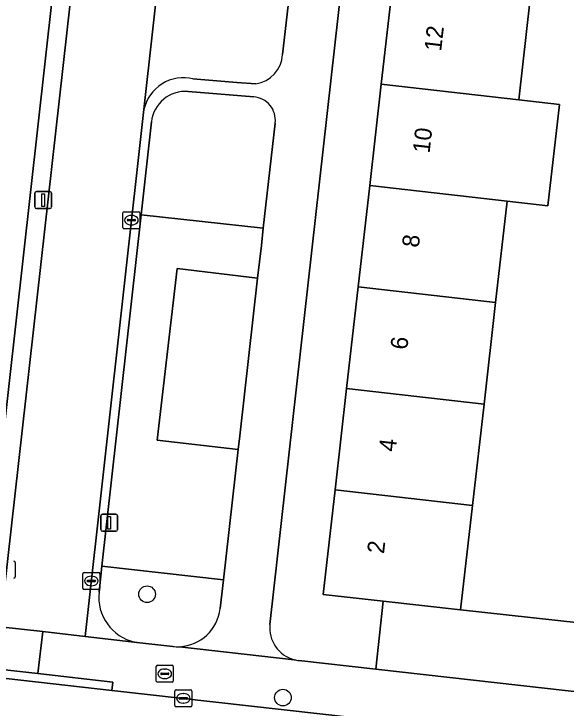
# Model space of a CAD drawing. Extents: x 161928 to 163071, y 386474 to 387428.
# Drawn here: x 162210.18 to 162242.64, y 386843.61 to 386884.42 of the extents above; entities that cross this region are included whole.
import ezdxf

# ---------------------------------------------------------------- set-up
doc = ezdxf.new("R2010")
doc.units = 0
for name, color, linetype in [('IMGEO_Boom', 7, 'Continuous'), ('IMGEO_Brandkraan', 7, 'Continuous'), ('IMGEO_Erf', 7, 'Continuous'), ('IMGEO_Groenvoorziening', 7, 'Continuous'), ('IMGEO_Hek', 7, 'Continuous'), ('IMGEO_Kolk', 7, 'Continuous'), ('IMGEO_Lichtmast', 7, 'Continuous'), ('IMGEO_Pand', 7, 'Continuous'), ('IMGEO_Pand_nummerreeks', 7, 'Continuous'), ('IMGEO_Parkeervlak_open', 7, 'Continuous'), ('IMGEO_Rijbaan_lokaal_open', 7, 'Continuous'), ('IMGEO_Voetpad_open', 7, 'Continuous')]:
    doc.layers.add(name, color=color, linetype=linetype)

msp = doc.modelspace()

# ---------------------------------------------------------------- linework, layer by layer
at = {"layer": 'IMGEO_Boom'}
for centre in [(162218.006, 386850.304), (162225.994, 386844.225)]:
    msp.add_circle(centre, 0.489, dxfattribs=at)
at = {"layer": 'IMGEO_Brandkraan'}
for p, q in [((162218.548, 386845.201), (162218.548, 386846.053)), ((162218.623, 386846.127), (162219.475, 386846.127)), ((162219.036, 386845.907), (162219.061, 386845.907)), ((162219.549, 386846.053), (162219.549, 386845.201)), ((162218.807, 386845.621), (162218.807, 386845.633)), ((162219.245, 386845.584), (162218.847, 386845.584)), ((162218.85, 386845.67), (162219.248, 386845.67)), ((162219.291, 386845.633), (162219.291, 386845.621)), ((162219.475, 386845.127), (162218.623, 386845.127)), ((162219.059, 386845.347), (162219.034, 386845.347))]:
    msp.add_line(p, q, dxfattribs=at)
for points in [[(162218.548, 386845.201), (162218.548, 386846.053)], [(162218.623, 386846.127), (162219.475, 386846.127)], [(162219.549, 386846.053), (162219.549, 386845.201)], [(162219.475, 386845.127), (162218.623, 386845.127)]]:
    msp.add_lwpolyline(points, dxfattribs=at)
for centre, radius, start, end in [((162218.625, 386846.051), 0.0765, 91.552, 178.448), ((162218.625, 386846.051), 0.0765, 91.552, 178.448), ((162219.473, 386846.051), 0.0765, 1.552, 88.448), ((162219.473, 386846.051), 0.0765, 1.552, 88.448), ((162218.847, 386845.63), 0.0403, 85.8775, 175.7526), ((162218.844, 386845.62), 0.0366, 178.938, 274.7102), ((162219.248, 386845.627), 0.043, 264.8664, 352.4533), ((162219.252, 386845.632), 0.0386, 1.7309, 96.639), ((162218.625, 386845.203), 0.0765, 181.552, 268.448), ((162218.625, 386845.203), 0.0765, 181.552, 268.448), ((162219.473, 386845.203), 0.0765, 271.552, 358.448), ((162219.473, 386845.203), 0.0765, 271.552, 358.448)]:
    msp.add_arc(centre, radius, start, end, dxfattribs=at)
for centre, major_axis, ratio, start_param, end_param in [((162219.035, 386845.627), (-0.387, 0.002), 0.722429, 4.712389, 7.853982), ((162219.06, 386845.627), (-0.39, 0.002), 0.717154, 1.570796, 4.712389)]:
    msp.add_ellipse(centre, major_axis=major_axis, ratio=ratio, start_param=start_param, end_param=end_param, dxfattribs=at)
at = {"layer": 'IMGEO_Erf'}
for points in [[(162208.562, 386850.925), (162215.453, 386912.353), (162212.452, 386912.769), (162211.772, 386906.681), (162211.096, 386900.626), (162210.454, 386894.884), (162209.763, 386888.694), (162209.094, 386882.707), (162208.433, 386876.788), (162207.776, 386870.913), (162207.09, 386864.77), (162206.45, 386859.042), (162205.758, 386852.844), (162197.649, 386853.75), (162194.899, 386854.057), (162195.575, 386860.111), (162198.325, 386859.804), (162198.341, 386859.947), (162198.981, 386865.675), (162199.667, 386871.818), (162200.324, 386877.693), (162200.985, 386883.612)], [(162231.776, 386880.288), (162232.455, 386886.249), (162233.134, 386892.21), (162233.812, 386898.172), (162234.491, 386904.133), (162235.191, 386910.281), (162232.179, 386910.543), (162225.231, 386848.529)], [(162240.531, 386885.329), (162239.853, 386879.368), (162242.246, 386879.095), (162241.567, 386873.133), (162239.174, 386873.406), (162238.496, 386867.444), (162237.817, 386861.482), (162237.138, 386855.521), (162236.439, 386849.378), (162244.833, 386848.474)], [(162226.925, 386846.407), (162231.457, 386845.899), (162231.888, 386849.896), (162228.362, 386850.297), (162229.062, 386856.442), (162229.74, 386862.403), (162230.419, 386868.365), (162231.098, 386874.326), (162231.776, 386880.288)]]:
    msp.add_lwpolyline(points, dxfattribs=at)
for centre, radius, start, end in [((162227.141, 386848.316), 1.922, 173.6367, 255.4109), ((162227.153, 386848.411), 2.016, 255.7652, 263.5123)]:
    msp.add_arc(centre, radius, start, end, dxfattribs=at)
at = {"layer": 'IMGEO_Groenvoorziening'}
for points in [[(162224.278, 386879.54), (162220.427, 386879.855)], [(162218.262, 386878.069), (162217.655, 386872.612), (162224.836, 386871.824), (162225.542, 386878.003)], [(162222.302, 386849.456), (162222.494, 386851.148), (162215.354, 386851.944), (162215.185, 386850.432)], [(162217.287, 386847.49), (162217.58, 386847.442), (162219.524, 386847.232)]]:
    msp.add_lwpolyline(points, dxfattribs=at)
for points in [[(162217.655, 386872.612), (162215.354, 386851.944), (162222.494, 386851.148), (162223.364, 386858.81), (162218.599, 386859.365), (162219.773, 386869.442), (162224.507, 386868.891), (162224.724, 386870.8), (162224.836, 386871.824)], [(162223.455, 386859.612), (162224.507, 386868.891), (162219.773, 386869.442), (162218.599, 386859.365), (162223.364, 386858.81)], [(162246.945, 386844.164), (162247.49, 386848.178), (162244.833, 386848.474), (162236.439, 386849.378), (162231.888, 386849.896), (162231.457, 386845.899)]]:
    msp.add_lwpolyline(points, close=True, dxfattribs=at)
for centre, radius, start, end in [((162220.264, 386877.847), 2.014, 85.3557, 173.6856), ((162224.166, 386878.16), 1.385, 353.4966, 85.3699), ((162217.87, 386850.128), 2.702, 173.5441, 257.546), ((162219.794, 386849.741), 2.524, 272.7401, 353.5183), ((162219.803, 386849.949), 2.731, 264.1357, 272.3485)]:
    msp.add_arc(centre, radius, start, end, dxfattribs=at)
at = {"layer": 'IMGEO_Hek'}
msp.add_lwpolyline([(162231.888, 386849.896), (162231.457, 386845.899)], dxfattribs=at)
at = {"layer": 'IMGEO_Kolk'}
for p, q in [((162216.585, 386871.864), (162216.585, 386872.716)), ((162216.66, 386872.79), (162217.512, 386872.79)), ((162217.073, 386872.57), (162217.098, 386872.57)), ((162217.586, 386872.716), (162217.586, 386871.864)), ((162216.844, 386872.284), (162216.844, 386872.296)), ((162217.282, 386872.247), (162216.884, 386872.247)), ((162216.887, 386872.333), (162217.285, 386872.333)), ((162217.096, 386872.01), (162217.071, 386872.01)), ((162217.328, 386872.296), (162217.328, 386872.284)), ((162217.512, 386871.79), (162216.66, 386871.79)), ((162210.25, 386852.178), (162210.25, 386851.326)), ((162214.229, 386850.658), (162214.229, 386851.51)), ((162214.304, 386851.584), (162215.156, 386851.584)), ((162214.717, 386851.364), (162214.742, 386851.364)), ((162215.23, 386851.51), (162215.23, 386850.658)), ((162214.488, 386851.078), (162214.488, 386851.09)), ((162214.926, 386851.041), (162214.528, 386851.041)), ((162214.531, 386851.127), (162214.929, 386851.127)), ((162214.74, 386850.804), (162214.715, 386850.804)), ((162214.972, 386851.09), (162214.972, 386851.078)), ((162215.156, 386850.584), (162214.304, 386850.584)), ((162219.71, 386844.686), (162220.562, 386844.686)), ((162219.635, 386843.76), (162219.635, 386844.612)), ((162220.123, 386844.466), (162220.148, 386844.466)), ((162220.636, 386844.612), (162220.636, 386843.76)), ((162219.894, 386844.18), (162219.894, 386844.192)), ((162220.332, 386844.143), (162219.934, 386844.143)), ((162219.937, 386844.229), (162220.335, 386844.229)), ((162220.146, 386843.906), (162220.121, 386843.906)), ((162220.378, 386844.192), (162220.378, 386844.18)), ((162220.562, 386843.686), (162219.71, 386843.686))]:
    msp.add_line(p, q, dxfattribs=at)
for points in [[(162216.585, 386871.864), (162216.585, 386872.716)], [(162216.66, 386872.79), (162217.512, 386872.79)], [(162217.586, 386872.716), (162217.586, 386871.864)], [(162217.512, 386871.79), (162216.66, 386871.79)], [(162210.25, 386852.178), (162210.25, 386851.326)], [(162214.229, 386850.658), (162214.229, 386851.51)], [(162214.304, 386851.584), (162215.156, 386851.584)], [(162215.23, 386851.51), (162215.23, 386850.658)], [(162215.156, 386850.584), (162214.304, 386850.584)], [(162219.71, 386844.686), (162220.562, 386844.686)], [(162219.635, 386843.76), (162219.635, 386844.612)], [(162220.636, 386844.612), (162220.636, 386843.76)], [(162220.562, 386843.686), (162219.71, 386843.686)]]:
    msp.add_lwpolyline(points, dxfattribs=at)
for centre, radius, start, end in [((162216.662, 386872.714), 0.0765, 91.552, 178.448), ((162216.662, 386872.714), 0.0765, 91.552, 178.448), ((162217.51, 386872.714), 0.0765, 1.552, 88.448), ((162217.51, 386872.714), 0.0765, 1.552, 88.448), ((162216.884, 386872.293), 0.0403, 85.8775, 175.7526), ((162216.881, 386872.283), 0.0366, 178.938, 274.7102), ((162217.285, 386872.29), 0.043, 264.8664, 352.4533), ((162217.289, 386872.295), 0.0386, 1.7309, 96.639), ((162216.662, 386871.866), 0.0765, 181.552, 268.448), ((162216.662, 386871.866), 0.0765, 181.552, 268.448), ((162217.51, 386871.866), 0.0765, 271.552, 358.448), ((162217.51, 386871.866), 0.0765, 271.552, 358.448), ((162210.174, 386852.176), 0.0765, 1.552, 88.448), ((162210.174, 386852.176), 0.0765, 1.552, 88.448), ((162210.174, 386851.328), 0.0765, 271.552, 358.448), ((162210.174, 386851.328), 0.0765, 271.552, 358.448), ((162214.306, 386851.508), 0.0765, 91.552, 178.448), ((162214.306, 386851.508), 0.0765, 91.552, 178.448), ((162215.154, 386851.508), 0.0765, 1.552, 88.448), ((162215.154, 386851.508), 0.0765, 1.552, 88.448), ((162214.528, 386851.087), 0.0403, 85.8775, 175.7526), ((162214.525, 386851.077), 0.0366, 178.938, 274.7102), ((162214.929, 386851.084), 0.043, 264.8664, 352.4533), ((162214.933, 386851.089), 0.0386, 1.7309, 96.639), ((162214.306, 386850.66), 0.0765, 181.552, 268.448), ((162214.306, 386850.66), 0.0765, 181.552, 268.448), ((162215.154, 386850.66), 0.0765, 271.552, 358.448), ((162215.154, 386850.66), 0.0765, 271.552, 358.448), ((162219.712, 386844.61), 0.0765, 91.552, 178.448), ((162219.712, 386844.61), 0.0765, 91.552, 178.448), ((162220.56, 386844.61), 0.0765, 1.552, 88.448), ((162220.56, 386844.61), 0.0765, 1.552, 88.448), ((162219.934, 386844.189), 0.0403, 85.8775, 175.7526), ((162219.931, 386844.179), 0.0366, 178.938, 274.7102), ((162220.335, 386844.186), 0.043, 264.8664, 352.4533), ((162220.339, 386844.191), 0.0386, 1.7309, 96.639), ((162219.712, 386843.762), 0.0765, 181.552, 268.448), ((162219.712, 386843.762), 0.0765, 181.552, 268.448), ((162220.56, 386843.762), 0.0765, 271.552, 358.448), ((162220.56, 386843.762), 0.0765, 271.552, 358.448)]:
    msp.add_arc(centre, radius, start, end, dxfattribs=at)
for centre, major_axis, ratio, start_param, end_param in [((162217.072, 386872.29), (-0.387, 0.002), 0.722429, 4.712389, 7.853982), ((162217.097, 386872.29), (-0.39, 0.002), 0.717154, 1.570796, 4.712389), ((162214.716, 386851.084), (-0.387, 0.002), 0.722429, 4.712389, 7.853982), ((162214.741, 386851.084), (-0.39, 0.002), 0.717154, 1.570796, 4.712389), ((162220.122, 386844.186), (-0.387, 0.002), 0.722429, 4.712389, 7.853982), ((162220.147, 386844.186), (-0.39, 0.002), 0.717154, 1.570796, 4.712389)]:
    msp.add_ellipse(centre, major_axis=major_axis, ratio=ratio, start_param=start_param, end_param=end_param, dxfattribs=at)
at = {"layer": 'IMGEO_Lichtmast'}
for p, q in [((162211.402, 386873.072), (162211.402, 386873.872)), ((162211.402, 386873.872), (162211.402, 386873.072)), ((162211.502, 386873.972), (162212.292, 386873.972)), ((162212.292, 386873.972), (162211.502, 386873.972)), ((162212.392, 386873.872), (162212.392, 386873.072)), ((162212.392, 386873.072), (162212.392, 386873.872)), ((162212.292, 386872.972), (162211.502, 386872.972)), ((162211.502, 386872.972), (162212.292, 386872.972)), ((162215.284, 386854.105), (162215.284, 386854.905)), ((162215.284, 386854.905), (162215.284, 386854.105)), ((162215.384, 386855.005), (162216.174, 386855.005)), ((162216.174, 386855.005), (162215.384, 386855.005)), ((162216.274, 386854.905), (162216.274, 386854.105)), ((162216.274, 386854.105), (162216.274, 386854.905)), ((162216.174, 386854.005), (162215.384, 386854.005)), ((162215.384, 386854.005), (162216.174, 386854.005))]:
    msp.add_line(p, q, dxfattribs=at)
for points in [[(162211.822, 386873.847), (162211.972, 386873.847), (162211.972, 386873.097), (162211.822, 386873.097), (162211.822, 386873.847)], [(162215.704, 386854.88), (162215.854, 386854.88), (162215.854, 386854.13), (162215.704, 386854.13), (162215.704, 386854.88)]]:
    msp.add_lwpolyline(points, dxfattribs=at)
for centre, start, end in [((162211.502, 386873.872), 90, 180), ((162211.502, 386873.872), 90, 180), ((162212.292, 386873.872), 0, 90), ((162212.292, 386873.872), 360, 90), ((162211.502, 386873.072), 180, 270), ((162211.502, 386873.072), 180, 270), ((162212.292, 386873.072), 270, 0), ((162212.292, 386873.072), 270, 0), ((162215.384, 386854.905), 90, 180), ((162215.384, 386854.905), 90, 180), ((162216.174, 386854.905), 0, 90), ((162216.174, 386854.905), 360, 90), ((162215.384, 386854.105), 180, 270), ((162215.384, 386854.105), 180, 270), ((162216.174, 386854.105), 270, 0), ((162216.174, 386854.105), 270, 0)]:
    msp.add_arc(centre, 0.1, start, end, dxfattribs=at)
at = {"layer": 'IMGEO_Pand'}
for points in [[(162239.853, 386879.368), (162240.531, 386885.329), (162232.455, 386886.249), (162231.776, 386880.288)], [(162239.853, 386879.368), (162231.776, 386880.288), (162231.098, 386874.326), (162239.174, 386873.406), (162241.567, 386873.133), (162242.246, 386879.095)], [(162231.098, 386874.326), (162230.419, 386868.365), (162238.496, 386867.444), (162239.174, 386873.406)], [(162237.817, 386861.482), (162238.496, 386867.444), (162230.419, 386868.365), (162229.74, 386862.403)], [(162229.74, 386862.403), (162229.062, 386856.442), (162237.138, 386855.521), (162237.817, 386861.482)], [(162229.062, 386856.442), (162228.362, 386850.297), (162231.888, 386849.896), (162236.439, 386849.378), (162237.138, 386855.521)]]:
    msp.add_lwpolyline(points, close=True, dxfattribs=at)
at = {"layer": 'IMGEO_Parkeervlak_open'}
for points in [[(162227.02, 386915.113), (162221.937, 386915.685), (162217.824, 386878.802)], [(162225.975, 386882.023), (162227.454, 386894.935), (162229.34, 386912.083)], [(162220.706, 386880.599), (162223.281, 386880.385), (162224.398, 386880.311)]]:
    msp.add_lwpolyline(points, dxfattribs=at)
for centre, radius, start, end in [((162224.144, 386882.128), 1.834, 277.9691, 356.7318), ((162220.155, 386878.273), 2.391, 76.6818, 167.2074)]:
    msp.add_arc(centre, radius, start, end, dxfattribs=at)
at = {"layer": 'IMGEO_Rijbaan_lokaal_open'}
for points in [[(162216.766, 386914.216), (162209.374, 386848.391), (162211.872, 386848.108), (162214.37, 386847.825), (162217.824, 386878.802), (162221.937, 386915.685)], [(162250, 386840.828), (162215.943, 386844.646), (162207.117, 386845.636), (162198.333, 386846.547), (162189.972, 386847.459), (162186.215, 386847.869), (162184.325, 386848.075), (162180.548, 386848.487), (162180.286, 386848.516)]]:
    msp.add_lwpolyline(points, dxfattribs=at)
at = {"layer": 'IMGEO_Voetpad_open'}
for points in [[(162206.167, 386848.791), (162209.374, 386848.391), (162216.766, 386914.216)], [(162215.669, 386914.282), (162215.453, 386912.353), (162208.562, 386850.925)], [(162229.34, 386912.083), (162227.454, 386894.935), (162225.975, 386882.023)], [(162225.231, 386848.529), (162232.179, 386910.543)], [(162224.398, 386880.311), (162223.281, 386880.385), (162220.706, 386880.599)], [(162220.427, 386879.855), (162224.278, 386879.54)], [(162217.824, 386878.802), (162214.37, 386847.825), (162217.58, 386847.442), (162217.287, 386847.49)], [(162215.185, 386850.432), (162215.354, 386851.944), (162217.655, 386872.612), (162218.262, 386878.069)], [(162225.542, 386878.003), (162224.836, 386871.824), (162224.724, 386870.8), (162224.507, 386868.891), (162223.455, 386859.612), (162223.364, 386858.81), (162222.494, 386851.148), (162222.302, 386849.456)], [(162180.286, 386848.516), (162180.548, 386848.487), (162184.325, 386848.075), (162186.215, 386847.869), (162189.972, 386847.459), (162198.333, 386846.547), (162207.117, 386845.636), (162207.172, 386846.133), (162211.585, 386845.638), (162211.872, 386848.108), (162209.374, 386848.391), (162206.167, 386848.791), (162205.913, 386848.805), (162197.071, 386849.812), (162190.344, 386850.578)], [(162219.524, 386847.232), (162217.58, 386847.442), (162214.37, 386847.825), (162211.872, 386848.108), (162211.585, 386845.638), (162215.998, 386845.143), (162215.943, 386844.646), (162250, 386840.828), (162265.838, 386838.97), (162272.289, 386838.281), (162272.9, 386843.099)], [(162219.915, 386847.22), (162226.657, 386846.456)], [(162226.657, 386846.456), (162219.915, 386847.22)], [(162261.606, 386842.521), (162248.649, 386843.973), (162246.945, 386844.164), (162231.457, 386845.899), (162226.925, 386846.407)]]:
    msp.add_lwpolyline(points, dxfattribs=at)
msp.add_lwpolyline([(162211.585, 386845.638), (162207.172, 386846.133), (162207.117, 386845.636), (162215.943, 386844.646), (162215.998, 386845.143)], close=True, dxfattribs=at)
for centre, radius, start, end in [((162224.144, 386882.128), 1.834, 277.9691, 356.7318), ((162220.155, 386878.273), 2.391, 76.6818, 167.2074), ((162220.264, 386877.847), 2.014, 85.3557, 173.6856), ((162224.166, 386878.16), 1.385, 353.4966, 85.3699), ((162217.87, 386850.128), 2.702, 173.5441, 257.546), ((162219.794, 386849.741), 2.524, 272.7401, 353.5183), ((162227.141, 386848.316), 1.922, 173.6367, 255.4109), ((162219.803, 386849.949), 2.731, 264.1357, 272.3485), ((162227.153, 386848.411), 2.016, 255.7652, 263.5123)]:
    msp.add_arc(centre, radius, start, end, dxfattribs=at)

# ---------------------------------------------------------------- texts
at = {"layer": 'IMGEO_Pand_nummerreeks'}
for s, rotation, p in [('12', 83.505, (162235.293, 386882.183)), ('10', 83.5029, (162234.61, 386876.19)), ('8', 83.505, (162233.981, 386870.65)), ('6', 83.505, (162233.298, 386864.648)), ('4', 83.505, (162232.615, 386858.65)), ('2', 83.505, (162231.931, 386852.649))]:
    msp.add_text(s, height=1, rotation=rotation, dxfattribs=at).set_placement(p)

doc.saveas('drawing.dxf')
